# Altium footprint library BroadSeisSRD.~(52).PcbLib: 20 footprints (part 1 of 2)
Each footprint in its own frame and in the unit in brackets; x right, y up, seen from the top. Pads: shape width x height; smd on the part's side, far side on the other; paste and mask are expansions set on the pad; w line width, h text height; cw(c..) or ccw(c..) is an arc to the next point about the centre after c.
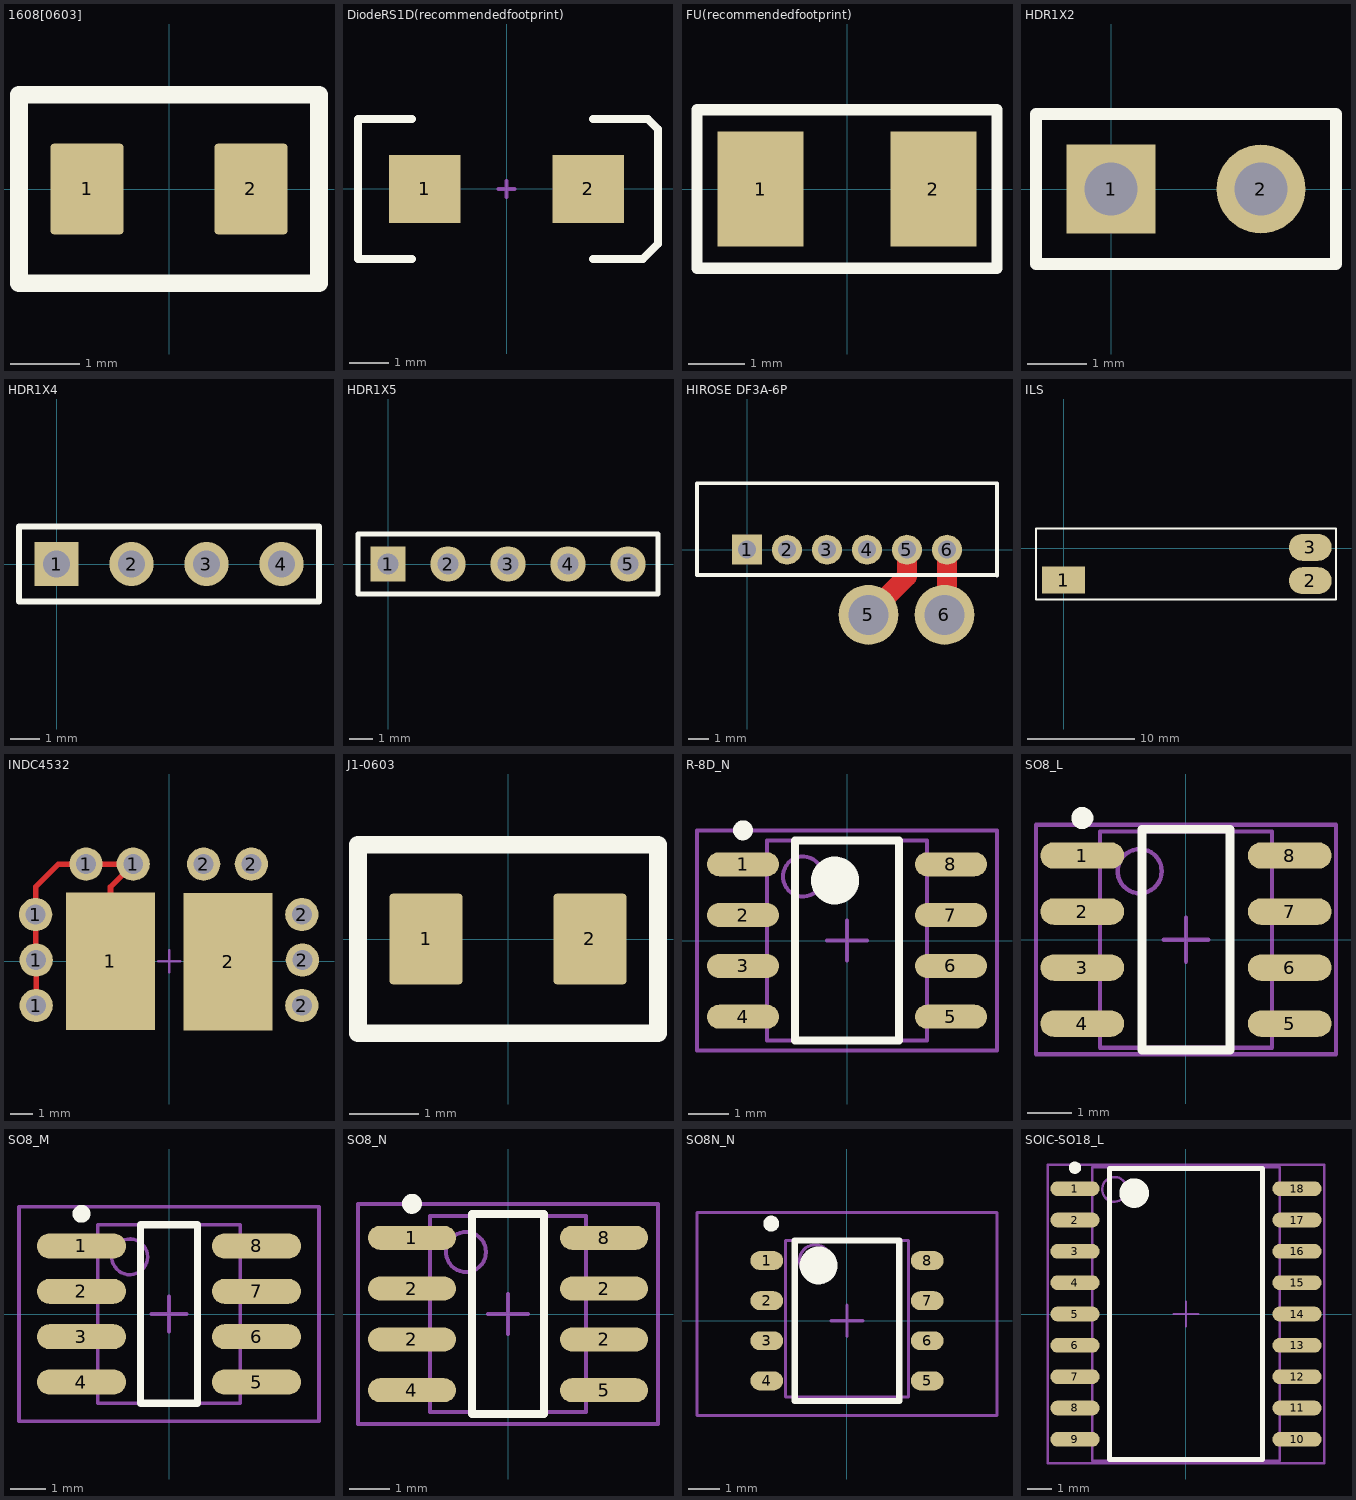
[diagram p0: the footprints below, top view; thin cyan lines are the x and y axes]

## 1608[0603] [mm] "Chip Capacitor, Body 1.6x0.8mm, IPC High Density"
height 1.3
pads (2):
  rrect10% 1.05x1.3 smd: 1(-1.175,0) 2(1.175,0)
Top Overlay:
  lines w0.254: -2.15,-1.35 -2.15,1.35 2.15,1.35 2.15,-1.35 -2.15,-1.35

## DiodeRS1D(recommendedfootprint) [mm] "DO-214-AB/SMC; 2 C-Bend Leads; Body 7.9 x 5.9 mm, inc. leads (LxW)"
height 2.65
pads (2):
  rect 1.8x1.7 smd: 1(-2.05,0) 2(2.05,0)
Top Overlay:
  lines w0.2: -2.375,-1.75 -3.725,-1.75 -3.725,1.75 -2.375,1.75 ; 2.175,-1.75 3.425,-1.75 3.8,-1.375 3.8,1.499 3.552,1.75 2.175,1.75
Mechanical 1:
  lines w0.1: -0.2,0 0.2,0 ; 0,-0.2 0,0.2

## FU(recommendedfootprint) [mm] "Thru-Hole; 2 Leads"
pads (2):
  rect 1.52x2.03 smd: 1(-1.525,0) 2(1.525,0)
Top Overlay:
  lines w0.2: -2.65,-1.4 2.65,-1.4 2.65,1.4 -2.65,1.4 -2.65,-1.4

## HDR1X2 [mm] "Connector; Header; 2 Position"
pads (2):
  rect 1.5x1.5 hole 0.9: 1(0,0)
  round 1.5 hole 0.9: 2(2.54,0)
Top Overlay:
  lines w0.2: -1.27,-1.27 -1.27,1.27 3.81,1.27 3.81,-1.27 -1.27,-1.27

## HDR1X4 [mm] "Connector; Header; 4 Position"
pads (4):
  rect 1.5x1.5 hole 0.9: 1(0,0)
  round 1.5 hole 0.9: 2(2.54,0) 3(5.08,0) 4(7.62,0)
Top Overlay:
  lines w0.2: -1.27,-1.27 8.89,-1.27 8.89,1.27 -1.27,1.27 -1.27,-1.27

## HDR1X5 [mm] "Connector; Header; 5 Position"
pads (5):
  rect 1.5x1.5 hole 0.9: 1(0,0)
  round 1.5 hole 0.9: 2(2.54,0) 3(5.08,0) 4(7.62,0) 5(10.16,0)
Top Overlay:
  lines w0.2: -1.27,-1.27 11.43,-1.27 11.43,1.27 -1.27,1.27 -1.27,-1.27

## HIROSE DF3A-6P [mm] "Connector; Header; 6 Position"
pads (8):
  rect 1.5x1.5 hole 0.9: 1(0,0)
  round 1.5 hole 0.9: 2(2,0) 3(4,0) 4(6,0) 5(8,0) 6(10,0)
  round 3 hole 2: 5(6.075,-3.25) 6(9.875,-3.25)
Top Layer:
  lines w0.254: 9.875,-3.25 10,-2.75
  lines w1: 6.075,-3.25 8,-1.325 8,0 ; 10,-2.75 10,0
Top Overlay:
  lines w0.2: 12.5,-1.29 12.5,3.325 -2.5,3.325 -2.5,-1.27 12.5,-1.27

## ILS [mm]
pads (3):
  rect 4x2.5 smd: 1(0,-2.95)
  oval 4x2.5 smd: 2(23,-3) 3(23,0.1)
Top Overlay:
  lines w0.2: -2.575,-4.775 25.4,-4.775 25.4,1.85 -2.575,1.85 -2.575,-4.775

## INDC4532 [mm] "Chip Inductor, Body 4.5x3.2mm, IPC High Density"
height 0.55
pads (12):
  round 1.5 hole 0.9: 1(-6.025,2.1) 1(-6,-2) 1(-6,0.05) 1(-3.75,4.375) 1(-1.625,4.375) 2(1.55,4.375) 2(3.7,4.375) 2(5.975,-2) 2(5.975,2.1) 2(6,0.05)
  rect 4x6.2 smd: 1(-2.65,0) 2(2.65,-0.025)
Top Layer:
  lines w0.254: -6,-2 -6,0.05 -6.025,0.075 -6.025,3.35 -5,4.375 -3.75,4.375 -1.625,4.375 -2.65,3.35 -2.65,0 -1.625,1.025
Mechanical 15:
  lines w0.1: -0.5,0 0.5,0 ; 0,-0.5 0,0.5

## J1-0603 [mm] "Chip Capacitor, Body 1.6x0.8mm, IPC High Density"
height 1.3
pads (2):
  rrect10% 1.05x1.3 smd: 1(-1.175,0) 2(1.175,0)
Top Overlay:
  lines w0.254: -2.15,-1.35 -2.15,1.35 2.15,1.35 2.15,-1.35 -2.15,-1.35

## R-8D_N [mm] "SOIC, 8-Leads, Body 4.9x3.9mm, Pitch 1.27mm, IPC Medium Density"
height 2.59
pads (8):
  oval 1.8x0.6 smd: 1(-2.6,1.905) 2(-2.6,0.635) 3(-2.6,-0.635) 4(-2.6,-1.905) 5(2.6,-1.905) 6(2.6,-0.635) 7(2.6,0.635) 8(2.6,1.905)
Top Overlay:
  circle w0.25: c-2.6,2.755 r0.125
  circle w0.6: c-0.3,1.5 r0.3
  lines w0.2: -1.3,-2.5 -1.3,2.5 1.3,2.5 1.3,-2.5 -1.3,-2.5
Mechanical 13:
  circle w0.1: c-1.1,1.6 r0.5
  lines w0.1: -2,-2.5 -2,2.5 2,2.5 2,-2.5 -2,-2.5
Mechanical 15:
  lines w0.1: -0.5,0 0.5,0 ; 0,-0.5 0,0.5 ; -3.75,-2.75 -3.75,2.75 3.75,2.75 3.75,-2.75 -3.75,-2.75
3D body: height 2.59, standoff 0, extent -2,-2.5 2,2.5

## SO8_L [mm] "SOIC, 8-Leads, Body 4.9x3.9mm, Pitch 1.27mm, IPC High Density"
height 1.75
pads (8):
  oval 1.9x0.6 smd: 1(-2.35,1.905) 2(-2.35,0.635) 3(-2.35,-0.635) 4(-2.35,-1.905) 5(2.35,-1.905) 6(2.35,-0.635) 7(2.35,0.635) 8(2.35,1.905)
Top Overlay:
  circle w0.25: c-2.35,2.755 r0.125
  lines w0.2: -1,-2.5 -1,2.5 1,2.5 1,-2.5 -1,-2.5
Mechanical 13:
  circle w0.1: c-1.05,1.55 r0.5
  lines w0.1: -1.95,-2.45 -1.95,2.45 1.95,2.45 1.95,-2.45 -1.95,-2.45
Mechanical 15:
  lines w0.1: -0.5,0 0.5,0 ; 0,-0.5 0,0.5 ; -3.4,-2.6 -3.4,2.6 3.4,2.6 3.4,-2.6 -3.4,-2.6
3D body: height 1.75, standoff 0, extent -1.95,-2.45 1.95,2.45

## SO8_M [mm] "SOIC, 8-Leads, Body 4.9x3.9mm, Pitch 1.27mm, IPC Low Density"
height 1.75
pads (8):
  oval 2.5x0.7 smd: 1(-2.45,1.905) 2(-2.45,0.635) 3(-2.45,-0.635) 4(-2.45,-1.905) 5(2.45,-1.905) 6(2.45,-0.635) 7(2.45,0.635) 8(2.45,1.905)
Top Overlay:
  circle w0.25: c-2.45,2.805 r0.125
  lines w0.2: -0.8,-2.5 0.8,-2.5 0.8,2.5 -0.8,2.5 -0.8,-2.5
Mechanical 13:
  circle w0.1: c-1.1,1.6 r0.5
  lines w0.1: -2,-2.5 2,-2.5 2,2.5 -2,2.5 -2,-2.5
Mechanical 15:
  lines w0.1: -0.5,0 0.5,0 ; 0,-0.5 0,0.5 ; -4.2,-3 4.2,-3 4.2,3 -4.2,3 -4.2,-3
3D body: height 1.75, standoff 0, extent -2,-2.5 2,2.5

## SO8_N [mm] "SOIC, 8-Leads, Body 4.9x3.9mm, Pitch 1.27mm, IPC Medium Density"
height 1.75
pads (8):
  oval 2.2x0.6 smd: 1(-2.4,1.905) 2(-2.4,-0.635) 2(-2.4,0.635) 2(2.4,-0.635) 2(2.4,0.635) 4(-2.4,-1.905) 5(2.4,-1.905) 8(2.4,1.905)
Top Overlay:
  circle w0.25: c-2.4,2.755 r0.125
  lines w0.2: -0.9,-2.5 -0.9,2.5 0.9,2.5 0.9,-2.5 -0.9,-2.5
Mechanical 13:
  circle w0.1: c-1.05,1.55 r0.5
  lines w0.1: -1.95,-2.45 -1.95,2.45 1.95,2.45 1.95,-2.45 -1.95,-2.45
Mechanical 15:
  lines w0.1: -0.5,0 0.5,0 ; 0,-0.5 0,0.5 ; -3.75,-2.75 -3.75,2.75 3.75,2.75 3.75,-2.75 -3.75,-2.75
3D body: height 1.75, standoff 0, extent -1.95,-2.45 1.95,2.45

## SO8N_N [mm] "SOP, 8-Leads, Body 5.3x5.3mm, Pitch 1.27mm, IPC Medium Density"
height 2.13
pads (8):
  oval 1.04x0.6 smd: 1(-2.54,1.905) 2(-2.54,0.635) 3(-2.54,-0.635) 4(-2.54,-1.905) 5(2.54,-1.905) 6(2.54,-0.635) 7(2.54,0.635) 8(2.54,1.905)
Top Overlay:
  circle w0.6: c-0.9,1.75 r0.3
  circle w0.25: c-2.4,3.075 r0.125
  lines w0.2: -1.651,-2.54 1.651,-2.54 1.651,2.54 -1.651,2.54 -1.651,-2.54
Mechanical 13:
  circle w0.1: c-1.008,1.905 r0.5
  lines w0.1: -1.95,-2.413 1.95,-2.413 1.95,2.54 -1.95,2.54 -1.95,-2.413
Mechanical 15:
  lines w0.1: -0.5,0 0.5,0 ; 0,-0.5 0,0.5 ; -4.75,-3 4.75,-3 4.75,3.425 -4.75,3.425 -4.75,-3
3D body: height 2.13, standoff 0, extent -2.286,-2.54 2.286,2.54

## SOIC-SO18_L [mm] "SOIC, 18-Leads, Body 11.5x7.5mm, Pitch 1.27mm, IPC High Density"
height 2.65
pads (18):
  oval 2x0.6 smd: 1(-4.5,5.08) 2(-4.5,3.81) 3(-4.5,2.54) 4(-4.5,1.27) 5(-4.5,0) 6(-4.5,-1.27) 7(-4.5,-2.54) 8(-4.5,-3.81) 9(-4.5,-5.08) 10(4.5,-5.08) 11(4.5,-3.81) 12(4.5,-2.54) 13(4.5,-1.27) 14(4.5,0) 15(4.5,1.27) 16(4.5,2.54) 17(4.5,3.81) 18(4.5,5.08)
Top Overlay:
  circle w0.25: c-4.5,5.93 r0.125
  circle w0.6: c-2.1,4.9 r0.3
  lines w0.2: -3.1,-5.9 -3.1,5.9 3.1,5.9 3.1,-5.9 -3.1,-5.9
Mechanical 13:
  circle w0.1: c-2.9,5.05 r0.5
  lines w0.1: -3.8,-5.95 -3.8,5.95 3.8,5.95 3.8,-5.95 -3.8,-5.95
Mechanical 15:
  lines w0.1: -0.5,0 0.5,0 ; 0,-0.5 0,0.5 ; -5.6,-6.05 -5.6,6.05 5.6,6.05 5.6,-6.05 -5.6,-6.05
3D body: height 2.65, standoff 0, extent -3.8,-5.95 3.8,5.95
